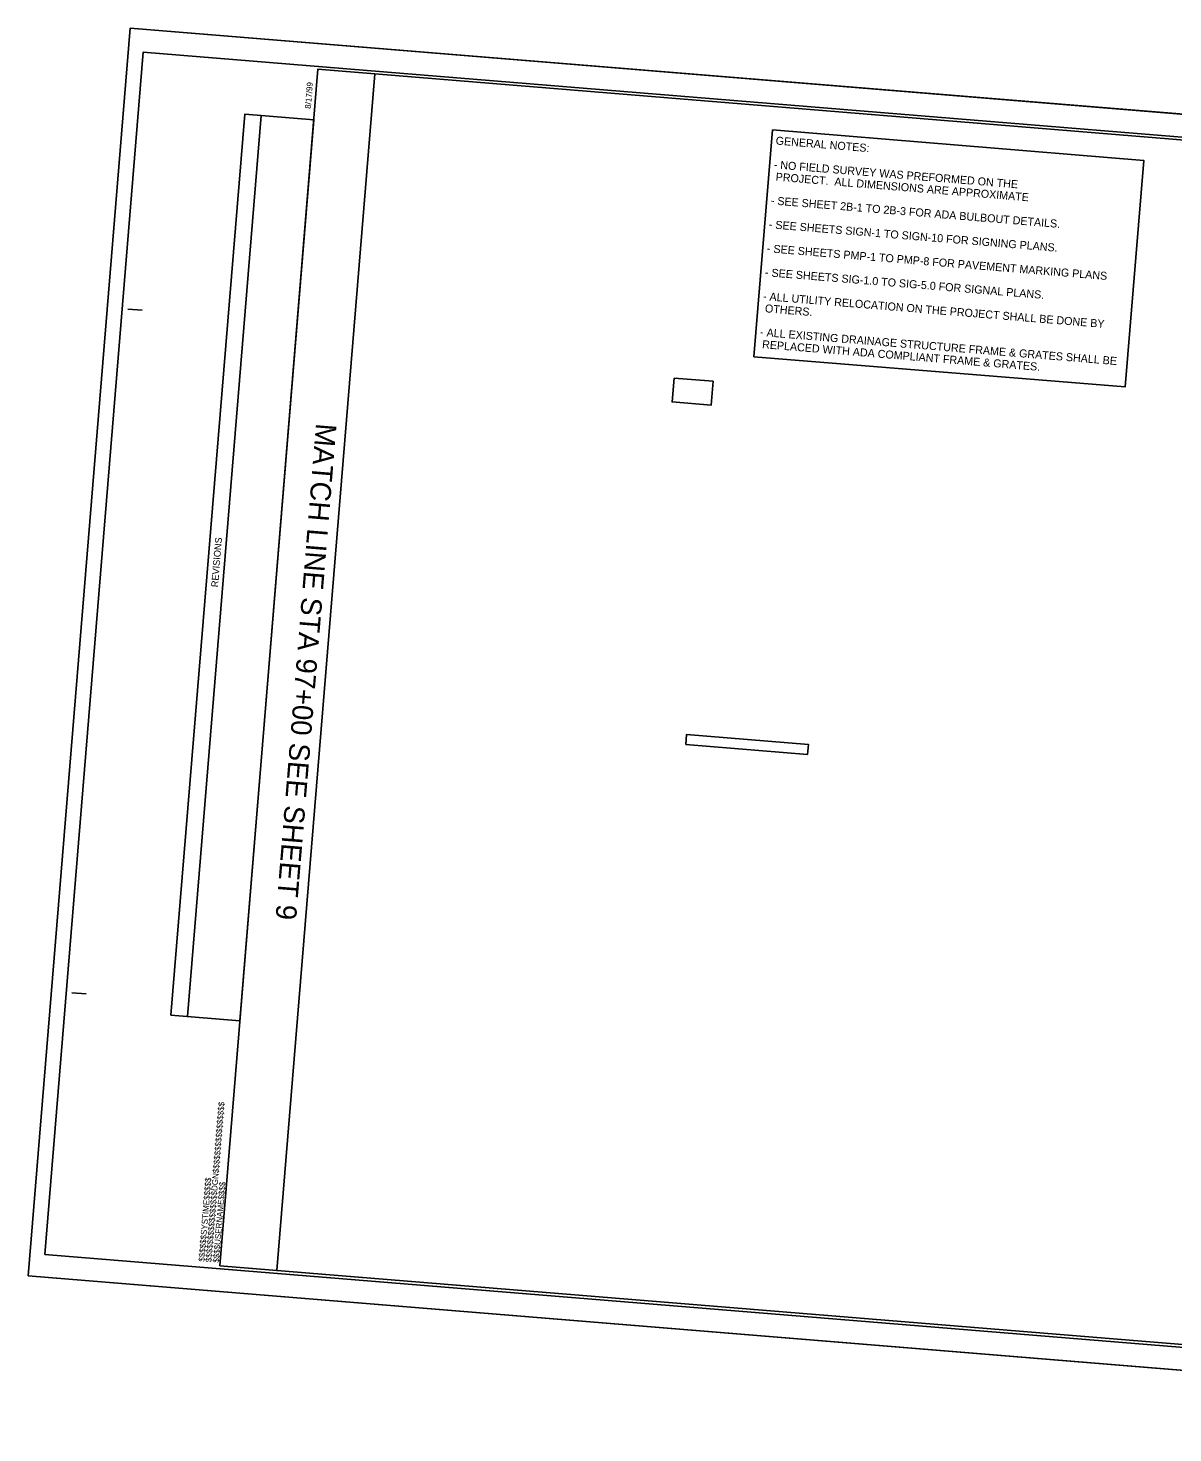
# Model space of a CAD drawing. Extents: x 935643 to 937646, y 683795 to 685023.
# Drawn here: x 935643 to 936645, y 683795 to 685023 of the extents above; entities that cross this region are included whole.
import ezdxf

# ---------------------------------------------------------------- set-up
doc = ezdxf.new("R2010")
doc.units = 0
for name, color, linetype in [('Prop Dimension', 7, 'Continuous'), ('Sheet Cutting Line CELL', 7, 'Continuous'), ('Sheet Layout Plan Border', 7, 'Continuous'), ('Sheet Plan CELL', 7, 'Continuous'), ('Sheet Plan Layout CELL', 7, 'Continuous'), ('Sheet Plot Border Inside CELL', 7, 'Continuous'), ('Sheet Plot Border Outside CELL', 7, 'Continuous'), ('Typical Text Grade Point CELL', 7, 'Continuous'), ('Typical Text Label CELL', 7, 'Continuous')]:
    doc.layers.add(name, color=color, linetype=linetype)

msp = doc.modelspace()

# ---------------------------------------------------------------- linework, layer by layer
at = {"layer": 'Prop Dimension'}
msp.add_line((935861, 683936.7), (935946.7, 684983.2), dxfattribs=at)
at = {"layer": 'Sheet Cutting Line CELL'}
for p, q in [((935732.7, 685023.3), (935643.4, 683931.9)), ((937410.6, 684886), (935732.7, 685023.3)), ((935643.4, 683931.9), (937321.3, 683794.6))]:
    msp.add_line(p, q, dxfattribs=at)
at = {"layer": 'Sheet Layout Plan Border'}
msp.add_line((935861, 683936.7), (935946.7, 684983.2), dxfattribs=at)
at = {"layer": 'Sheet Plan CELL'}
for p, q in [((935896.8, 684987.3), (935896.8, 684987.3)), ((935782.9, 684158.8), (935847.4, 684946.8)), ((935730.7, 684777.6), (935743.1, 684776.6)), ((935681.8, 684179.6), (935694.2, 684178.6)), ((935811.2, 683940.8), (935811.2, 683940.8))]:
    msp.add_line(p, q, dxfattribs=at)
for points in [[(937391.9, 684865), (935896.8, 684987.3), (935811.2, 683940.8), (937306.2, 683818.5)], [(935768.4, 684160), (935832.9, 684948), (935893.2, 684943.1), (935828.7, 684155.1)]]:
    msp.add_lwpolyline(points, close=True, dxfattribs=at)
at = {"layer": 'Sheet Plan Layout CELL'}
msp.add_lwpolyline([(935896.8, 684987.3), (935811.2, 683940.8), (937306.2, 683818.5), (937374.6, 684654.2), (937136.1, 684673.7), (937153.4, 684884.5)], close=True, dxfattribs=at)
at = {"layer": 'Sheet Plot Border Inside CELL'}
msp.add_lwpolyline([(935658, 683950.8), (937318.5, 683815), (937404.5, 684866.4), (935744.1, 685002.3)], close=True, dxfattribs=at)
at = {"layer": 'Sheet Plot Border Outside CELL'}
msp.add_lwpolyline([(935643.4, 683931.9), (937321.3, 683794.6), (937410.6, 684886), (935732.7, 685023.3)], close=True, dxfattribs=at)
at = {"layer": 'Typical Text Grade Point CELL'}
for points in [[(936294.6, 684934.2), (936619.2, 684907.6), (936602.9, 684709.4), (936278.3, 684735.9)], [(936208.5, 684717.2), (936242.6, 684714.4), (936240.8, 684693.5), (936206.7, 684696.3)], [(936218.6, 684396.8), (936325.2, 684388.1), (936325.9, 684396.8), (936219.3, 684405.6)]]:
    msp.add_lwpolyline(points, close=True, dxfattribs=at)

# ---------------------------------------------------------------- texts
at = {"layer": 'Sheet Plan CELL'}
for s, height, p in [('8/17/99', 5.25, (935890.7, 684952.5)), ('REVISIONS', 6, (935809.5, 684534.1)), ('$$$$$$$$$$$$$$$$DGN$$$$$$$$$$$$$$$$', 5.25, (935803.8, 683943.8)), ('$$$$$$SYSTIME$$$$$', 5.25, (935797.7, 683944.2)), ('$$$$USERNAME$$$$', 5.25, (935810.3, 683943.3))]:
    msp.add_text(s, height=height, rotation=85.3221, dxfattribs=at).set_placement(p)
at = {"layer": 'Typical Text Grade Point CELL'}
for s, p in [('GENERAL NOTES:', (936297.1, 684921.5)), ('- NO FIELD SURVEY WAS PREFORMED ON THE ', (936295.4, 684900.6)), (' PROJECT.  ALL DIMENSIONS ARE APPROXIMATE', (936294.5, 684890.1)), ('- SEE SHEET 2B-1 TO 2B-3 FOR ADA BULBOUT DETAILS.', (936292.8, 684869.2)), ('- SEE SHEETS SIGN-1 TO SIGN-10 FOR SIGNING PLANS.', (936291.1, 684848.3)), ('- SEE SHEETS PMP-1 TO PMP-8 FOR PAVEMENT MARKING PLANS  ', (936289.4, 684827.3)), ('- SEE SHEETS SIG-1.0 TO SIG-5.0 FOR SIGNAL PLANS.', (936287.7, 684806.4)), ('- ALL UTILITY RELOCATION ON THE PROJECT SHALL BE DONE BY ', (936286, 684785.5)), (' OTHERS.', (936285.1, 684775)), ('- ALL EXISTING DRAINAGE STRUCTURE FRAME & GRATES SHALL BE ', (936283.4, 684754.1)), (' REPLACED WITH ADA COMPLIANT FRAME & GRATES.', (936282.6, 684743.6))]:
    msp.add_text(s, height=7, rotation=355.3221, dxfattribs=at).set_placement(p)
at = {"layer": 'Typical Text Label CELL'}
msp.add_text('MATCH LINE STA 97+00 SEE SHEET 9 ', height=18, rotation=265.3221, dxfattribs=at).set_placement((935895.3, 684678))

doc.saveas('drawing.dxf')
